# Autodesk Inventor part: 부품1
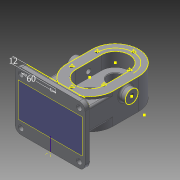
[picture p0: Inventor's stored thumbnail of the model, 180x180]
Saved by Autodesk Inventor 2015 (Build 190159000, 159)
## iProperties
Created: 2020-09
Part Number: 부품1
Material: 일반
Document SubType Name: Modeling
Designer: Main
Density: 1 g/cm^3
Appearance: 기본값
Author: Main
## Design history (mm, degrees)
sketch "스케치2"
  geometry: L1 (0, 0)-(0, -44); L2 (-40, 0)-(-40, -44); L3 (40, -44)-(40, 0); L4 (0, 0)-(0, -44); L5 (-24, 0)-(-24, -44); L6 (24, -44)-(24, 0); L7 (0, 0)-(0, -44); L8 (-31, 0)-(-31, -44); L9 (31, -44)-(31, 0); C1 r 12.5 at (0, 0); C2 r 12.5 at (0, -44); A1 r 40 centre (0, 0) between (40, 0) and (-40, 0); A2 r 40 centre (0, -44) between (-40, -44) and (40, -44); A3 r 24 centre (0, 0) between (24, 0) and (-24, 0); A4 r 24 centre (0, -44) between (-24, -44) and (24, -44); A5 r 31 centre (0, 0) between (31, 0) and (-31, 0); A6 r 31 centre (0, -44) between (-31, -44) and (31, -44); 3 further points
  constraints: 24 end point, 12 point on circle, 12 tangent, 8 centre point, 5 equal length, 3 midpoint, 2 coincident, 1 vertical
extrude "돌출1" new body sketch "스케치2" distance "d2" = 29; taper "d3" = 0 deg
extrude "돌출2" join sketch "스케치2" distance "d4" = 53; taper "d5" = 0 deg
extrude "돌출3" join sketch "스케치2" distance "d6" = 14; taper "d7" = 0 deg
sketch "스케치3"
  geometry: L1 (24, 0)-(24, -44) reference; L2 (-24, -44)-(-24, 0) reference; L3 (-40, 0)-(-40, -44) reference; L4 (40, -44)-(40, 0) reference; L5 (24, 0)-(24, -44) reference; L6 (-24, -44)-(-24, 0) reference; L7 (-40, 0)-(-40, -44) reference; L8 (40, -44)-(40, 0) reference; A1 r 24 centre (0, 0) between (24, 0) and (-24, 0) reference; A2 r 24 centre (0, -44) between (-24, -44) and (24, -44) reference; A3 r 40 centre (0, -44) between (-40, -44) and (40, -44) reference; A4 r 40 centre (0, 0) between (40, 0) and (-40, 0) reference; A5 r 31 centre (0, 0) between (31, 0) and (-31, 0) reference; A6 r 24 centre (0, 0) between (24, 0) and (-24, 0) reference; A7 r 24 centre (0, -44) between (-24, -44) and (24, -44) reference; A8 r 40 centre (0, -44) between (-40, -44) and (40, -44) reference; A9 r 40 centre (0, 0) between (40, 0) and (-40, 0) reference
  node "투영된 루프1"
node "작업 평면1"
sketch "스케치4"
  geometry: L1 (0, 53)-(-44, 53) reference; L2 (-22, 53)-(-22, 39); C1 r 11 at (-22, 39); 1 further point
  constraints: 2 end point, 1 centre point, 1 coincident, 1 midpoint, 1 vertical
extrude "돌출4" join sketch "스케치4" distance "d9" = 10; taper "d10" = 0 deg
sketch "스케치5"
  geometry: C1 r 11 at (0, 0) reference; 1 further point
hole "구멍1" diameter "d13" = 8.376; stored, may be unused: countersink angle "d17" = 90 deg, drill point angle "d19" = 118 deg; dims "d11" = 10, "d12" = 10, "d14" = 20, "d15" = 4, "d16" = 2, "d18" = 27.3
node "작업 평면2"
sketch "스케치6"
  geometry: L1 (-40, 0)-(-40, 53) reference; L2 (-40, 26.5)-(40, 26.5); L3 (40, 0)-(40, 53) reference; L4 (-60, 76.5)-(60, 76.5); L5 (60, 76.5)-(60, -23.5); L6 (60, -23.5)-(-60, -23.5); L7 (-60, -23.5)-(-60, 76.5); L8 (-60, 76.5)-(60, -23.5); L9 (60, 76.5)-(-60, -23.5); 2 further points
  constraints: 14 end point, 5 midpoint, 2 parallel, 1 horizontal, 1 perpendicular
extrude "돌출5" join sketch "스케치6" distance "d21" = 10; taper "d22" = 0 deg
fillet "모깎기1" dims "d23" = 10
sketch "스케치7"
  geometry: C1 r 4.5 at (-50, 13.5); C2 r 4.5 at (50, 13.5); C3 r 4.5 at (50, -66.5); C4 r 4.5 at (-50, -66.5); A1 r 10 centre (50, 13.5) between (60, 13.5) and (50, 23.5) reference; A2 r 10 centre (-50, 13.5) between (-50, 23.5) and (-60, 13.5) reference; A3 r 10 centre (-50, -66.5) between (-60, -66.5) and (-50, -76.5) reference; A4 r 10 centre (50, -66.5) between (50, -76.5) and (60, -66.5) reference; 1 further point
  constraints: 4 centre point, 4 coincident
extrude "돌출6" cut sketch "스케치7" distance "d24" = 10; taper "d25" = 0 deg
sketch "스케치8"
  geometry: 1 further point
sketch "스케치9"
  geometry: L1 (-112, -23.5)-(-112, 0); 1 further point
  constraints: 2 end point, 1 vertical
node "작업 평면3"
sketch "스케치10"
  geometry: L1 (0, -102)-(-40, -102); L2 (50, -102)-(-50, -102) reference; L3 (-40, -102)-(-40, -44); L4 (-40, 0)-(-40, -44) reference; L5 (0, -102)-(40, -102); L6 (40, -102)-(40, -44); A1 r 40 centre (0, -44) between (-40, -44) and (40, -44) reference; A2 r 40 centre (0, -44) between (-40, -44) and (40, -44); 1 further point
  constraints: 8 end point, 3 tangent, 2 point on circle, 2 point on line, 1 centre point, 1 collinear, 1 perpendicular
extrude "돌출7" join sketch "스케치10" distance "d27" = 37; taper "d28" = 0 deg
fillet "모깎기2" dims "d29" = 3
node "작업 평면4"
sketch "스케치11"
  geometry: C1 r 12.5 at (0, 0) reference; C2 r 8.5 at (0, 0); C3 r 14 at (0, 0); C4 r 19 at (0, 0); 1 further point
  constraints: 3 centre point, 3 coincident
extrude "돌출8" join sketch "스케치11" distance "d31" = 17; taper "d32" = 0 deg
extrude "돌출9" cut sketch "스케치11" distance "d33" = 8; taper "d34" = 0 deg
extrude "돌출10" cut sketch "스케치11" distance "d35" = 40; taper "d36" = 0 deg
sketch "스케치12"
  geometry: L1 (0, 0)-(0, -44); L2 (-31, 0)-(-31, -44); L3 (31, -44)-(31, 0); A1 r 40 centre (0, -44) between (-40, -44) and (40, -44) reference; A2 r 40 centre (0, 0) between (40, 0) and (-40, 0) reference; A3 r 31 centre (0, 0) between (31, 0) and (-31, 0); A4 r 31 centre (0, -44) between (-31, -44) and (31, -44); A5 r 31 centre (0, 0) between (31, 0) and (-31, 0) reference; 2 further points
  constraints: 8 end point, 4 point on circle, 4 tangent, 2 centre point, 1 midpoint, 1 parallel, 1 vertical
sketch "스케치13"
  geometry: L1 (24, 0)-(24, -44) reference; L2 (-24, -44)-(-24, 0) reference; L3 (-40, 0)-(-40, -44) reference; L4 (40, -44)-(40, 0) reference; A1 r 24 centre (0, 0) between (24, 0) and (-24, 0) reference; A2 r 24 centre (0, -44) between (-24, -44) and (24, -44) reference; A3 r 40 centre (0, -44) between (-40, -44) and (40, -44) reference; A4 r 40 centre (0, 0) between (40, 0) and (-40, 0) reference
sketch "스케치14"
  geometry: L1 (0, -75.027)-(0, 30.955); L2 (-31.226, -44)-(24, -44); L3 (-50, -17.812)-(-24, -17.812) reference; L4 (-31.226, 0)-(24, 0)
  constraints: 6 end point, 2 parallel, 1 vertical
node "작업점1"
node "작업점2"
node "작업점3"
node "작업점4"
node "작업점5"
node "작업점6"
hole "구멍2" diameter "d39" = 4.134; stored, may be unused: countersink angle "d43" = 90 deg, drill point angle "d45" = 118 deg; dims "d37" = 10, "d38" = 10, "d40" = 10, "d41" = 4, "d42" = 2, "d44" = 12
hole "구멍3" sketch "스케치14" diameter "d46" = 4.134; stored, may be unused: countersink angle "d50" = 90 deg, drill point angle "d52" = 118 deg; dims "d47" = 10, "d48" = 4, "d49" = 2, "d51" = 12
hole "구멍4" sketch "스케치12" diameter "d53" = 4.134; stored, may be unused: countersink angle "d57" = 90 deg, drill point angle "d59" = 118 deg; dims "d54" = 10, "d55" = 4, "d56" = 2, "d58" = 12
hole "구멍5" diameter "d62" = 4.134; stored, may be unused: countersink angle "d66" = 90 deg, drill point angle "d68" = 118 deg; dims "d60" = 10, "d61" = 10, "d63" = 10, "d64" = 4, "d65" = 2, "d67" = 12
sketch "스케치15"
  geometry: L1 (-43, -14.5)-(-43, -45.5) reference; L2 (37, -8.5)-(-37, -8.5) reference; L3 (43, -45.5)-(43, -14.5) reference; L4 (-37, -51.5)-(37, -51.5) reference; L5 (57, 13.5)-(57, -66.5) reference; L6 (-50, 20.5)-(50, 20.5) reference; L7 (-57, -66.5)-(-57, 13.5) reference; L8 (50, -73.5)-(-50, -73.5) reference; L9 (-50, -76.5)-(50, -76.5) reference; L10 (-60, 13.5)-(-60, -66.5) reference; C1 r 4.5 at (50, -66.5) reference; C2 r 4.5 at (-50, 13.5) reference; C3 r 4.5 at (50, 13.5) reference; C4 r 4.5 at (-50, -66.5) reference; A1 r 6 centre (-37, -45.5) between (-43, -45.5) and (-37, -51.5) reference; A2 r 6 centre (-37, -14.5) between (-37, -8.5) and (-43, -14.5) reference; A3 r 6 centre (37, -14.5) between (43, -14.5) and (37, -8.5) reference; A4 r 6 centre (37, -45.5) between (37, -51.5) and (43, -45.5) reference; A5 r 7 centre (50, -66.5) between (50, -73.5) and (57, -66.5) reference; A6 r 7 centre (50, 13.5) between (57, 13.5) and (50, 20.5) reference; A7 r 7 centre (-50, 13.5) between (-50, 20.5) and (-57, 13.5) reference; A8 r 7 centre (-50, -66.5) between (-57, -66.5) and (-50, -73.5) reference; 2 further points
  constraints: 1 other
  dimensions: "d69" = 12 distance from line of L9 point (0, -64.5); "d70" = 60 distance from line of L10 point (0, -64.5)
fillet "모깎기3" dims "d71" = 3
chamfer "모따기1" distance "d72" = 1; stored, may be unused: second distance "d73" = 2, angle "d74" = 45 deg
chamfer "모따기2" distance "d75" = 1; stored, may be unused: second distance "d76" = 2, angle "d77" = 45 deg
fillet "모깎기4" dims "d78" = 3
node "솔리드1"
mirror "대칭1"
other parameters: "d20" = -112, "d26" = 11.5, "d30" = -17
